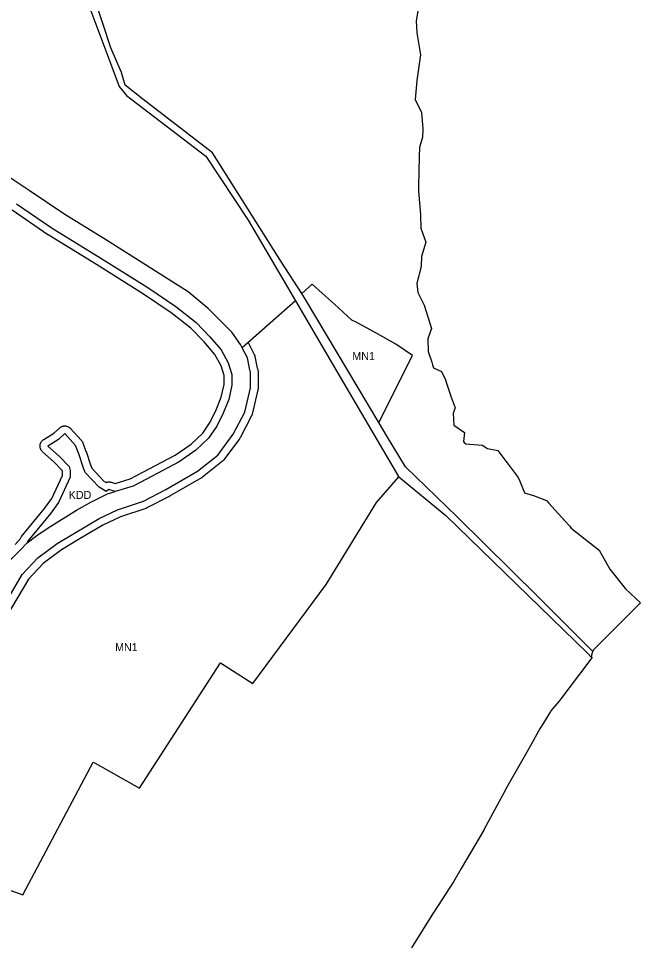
# Model space of a CAD drawing. Extents: x 7435758 to 7439981, y 5550649 to 5554049.
# Drawn here: x 7439577 to 7439981, y 5552845 to 5553445 of the extents above; entities that cross this region are included whole.
import ezdxf

# ---------------------------------------------------------------- set-up
doc = ezdxf.new("R2010")
doc.units = 0
for name, color, linetype in [('linie_rozgraniczające', 7, 'Continuous'), ('linie_zabudowy_nieprzekraczalne', 7, 'Continuous'), ('oznaczenia_przeznaczen', 7, 'Continuous')]:
    doc.layers.add(name, color=color, linetype=linetype)

msp = doc.modelspace()

# ---------------------------------------------------------------- linework, layer by layer
at = {"layer": 'linie_rozgraniczające'}
for p, q in [((7439600.88, 5553512.3), (7439637.66, 5553413.68)), ((7439636.99, 5553425.88), (7439626.65, 5553457.88)), ((7439837.74, 5553455.94), (7439835.78, 5553444.79)), ((7439835.78, 5553444.79), (7439835.56, 5553443.54)), ((7439835.56, 5553443.54), (7439836.05, 5553435.64)), ((7439836.05, 5553435.64), (7439838.25, 5553421.48)), ((7439644.02, 5553409.86), (7439636.99, 5553425.88)), ((7439838.25, 5553421.48), (7439836.79, 5553410.83)), ((7439637.66, 5553413.68), (7439642.44, 5553400.76)), ((7439836.79, 5553410.83), (7439835.95, 5553404.71)), ((7439646.47, 5553401.81), (7439644.02, 5553409.86)), ((7439835.95, 5553404.71), (7439834.94, 5553392.49)), ((7439642.44, 5553400.76), (7439647.28, 5553394.93)), ((7439657.82, 5553392.7), (7439646.47, 5553401.81)), ((7439647.28, 5553394.93), (7439698.84, 5553355.57)), ((7439703.19, 5553357.69), (7439657.82, 5553392.7)), ((7439834.94, 5553392.49), (7439839.02, 5553383.87)), ((7439839.02, 5553383.87), (7439839.82, 5553373.41)), ((7439839.82, 5553373.41), (7439839.62, 5553367.85)), ((7439839.62, 5553367.85), (7439837.58, 5553361.13)), ((7439748.06, 5553286.69), (7439703.19, 5553357.69)), ((7439837.58, 5553361.13), (7439837.46, 5553355.42)), ((7439698.84, 5553355.57), (7439726.22, 5553313.97)), ((7439837.46, 5553355.42), (7439837.26, 5553345.78)), ((7439584.03, 5553333.24), (7439566.36, 5553345.02)), ((7439837.26, 5553345.78), (7439837.06, 5553335.9)), ((7439607.06, 5553317.76), (7439584.03, 5553333.24)), ((7439837.06, 5553335.9), (7439837, 5553332.75)), ((7439837, 5553332.75), (7439838.27, 5553317.73)), ((7439575.65, 5553324.69), (7439598.96, 5553308.71)), ((7439634.18, 5553301.02), (7439607.06, 5553317.76)), ((7439838.27, 5553317.73), (7439838.33, 5553317.13)), ((7439838.33, 5553317.13), (7439838.65, 5553308.8)), ((7439598.96, 5553308.71), (7439630.48, 5553289.41)), ((7439726.22, 5553313.97), (7439757.05, 5553261.56)), ((7439838.65, 5553308.8), (7439841.86, 5553299.67)), ((7439687.37, 5553267.5), (7439634.18, 5553301.02)), ((7439841.2, 5553297.6), (7439838.89, 5553290.32)), ((7439841.86, 5553299.67), (7439841.2, 5553297.6)), ((7439630.48, 5553289.41), (7439661.08, 5553270.21)), ((7439761.15, 5553266.28), (7439748.06, 5553286.69)), ((7439838.89, 5553290.32), (7439838.76, 5553284.12)), ((7439838.76, 5553284.12), (7439836.94, 5553276.97)), ((7439836.58, 5553275.58), (7439835.91, 5553272.94)), ((7439835.91, 5553272.94), (7439836.66, 5553266.92)), ((7439836.94, 5553276.97), (7439836.58, 5553275.58)), ((7439661.08, 5553270.21), (7439679.29, 5553257.92)), ((7439700.31, 5553256.56), (7439687.37, 5553267.5)), ((7439767.84, 5553272.4), (7439761.15, 5553266.28)), ((7439774.65, 5553266.36), (7439767.84, 5553272.4)), ((7439836.66, 5553266.92), (7439836.85, 5553266.54)), ((7439757.05, 5553261.56), (7439722.38, 5553231.16)), ((7439757.05, 5553261.56), (7439786.17, 5553212.04)), ((7439763.57, 5553262.51), (7439761.15, 5553266.28)), ((7439811.19, 5553182.58), (7439763.57, 5553262.51)), ((7439782.48, 5553259.39), (7439774.65, 5553266.36)), ((7439836.85, 5553266.54), (7439840.75, 5553258.73)), ((7439679.29, 5553257.92), (7439692.48, 5553247.52)), ((7439715.78, 5553241.3), (7439700.31, 5553256.56)), ((7439793.78, 5553249.03), (7439782.48, 5553259.39)), ((7439840.75, 5553258.73), (7439840.76, 5553258.7)), ((7439840.76, 5553258.7), (7439845.51, 5553243.61)), ((7439796.53, 5553247.7), (7439793.78, 5553249.03)), ((7439692.48, 5553247.52), (7439701.45, 5553238.25)), ((7439810.35, 5553240.21), (7439796.53, 5553247.7)), ((7439845.51, 5553243.61), (7439843.47, 5553238.15)), ((7439701.45, 5553238.25), (7439708.83, 5553229.69)), ((7439721.32, 5553233.19), (7439715.78, 5553241.3)), ((7439822.25, 5553233.53), (7439810.35, 5553240.21)), ((7439843.47, 5553238.15), (7439843.02, 5553236.95)), ((7439843.02, 5553236.95), (7439843.39, 5553228.59)), ((7439722.38, 5553231.16), (7439721.32, 5553233.19)), ((7439725.84, 5553224.52), (7439722.38, 5553231.16)), ((7439833.15, 5553226.11), (7439822.25, 5553233.53)), ((7439708.83, 5553229.69), (7439713.34, 5553221.28)), ((7439811.19, 5553182.58), (7439833.15, 5553226.11)), ((7439843.39, 5553228.59), (7439845.62, 5553221.73)), ((7439713.34, 5553221.28), (7439715.72, 5553213.82)), ((7439727.46, 5553216.51), (7439725.84, 5553224.52)), ((7439845.62, 5553221.73), (7439846.16, 5553220.07)), ((7439846.16, 5553220.07), (7439846.79, 5553218.12)), ((7439715.72, 5553213.82), (7439715.75, 5553206.79)), ((7439727.74, 5553215.81), (7439727.46, 5553216.51)), ((7439727.8, 5553205.01), (7439727.74, 5553215.81)), ((7439846.79, 5553218.12), (7439851.88, 5553215.65)), ((7439851.88, 5553215.65), (7439854.6, 5553210.39)), ((7439715.75, 5553206.79), (7439713.65, 5553197.46)), ((7439786.17, 5553212.04), (7439824.05, 5553147.49)), ((7439854.6, 5553210.39), (7439855.76, 5553206.77)), ((7439855.76, 5553206.77), (7439858.21, 5553199.09)), ((7439724.05, 5553189.22), (7439727.8, 5553205.01)), ((7439713.65, 5553197.46), (7439710.1, 5553188.72)), ((7439858.21, 5553199.09), (7439860.93, 5553192.09)), ((7439716.67, 5553174.92), (7439724.05, 5553189.22)), ((7439860.93, 5553192.09), (7439859.66, 5553188.64)), ((7439710.1, 5553188.72), (7439706.02, 5553180.22)), ((7439859.66, 5553188.64), (7439860.08, 5553180.94)), ((7439706.02, 5553180.22), (7439700.6, 5553172.44)), ((7439816.24, 5553174.11), (7439811.19, 5553182.58)), ((7439860.08, 5553180.94), (7439866.96, 5553176.05)), ((7439603.12, 5553171.56), (7439596.04, 5553167.28)), ((7439607.13, 5553175.34), (7439603.12, 5553171.56)), ((7439614.15, 5553167.65), (7439607.13, 5553175.34)), ((7439700.6, 5553172.44), (7439692.33, 5553164.56)), ((7439706.52, 5553161.34), (7439716.67, 5553174.92)), ((7439828.58, 5553153.88), (7439816.24, 5553174.11)), ((7439866.96, 5553176.05), (7439866.17, 5553170.16)), ((7439596.04, 5553167.28), (7439603.38, 5553160.69)), ((7439616.19, 5553162.12), (7439614.15, 5553167.65)), ((7439866.17, 5553170.16), (7439866.69, 5553169.69)), ((7439866.69, 5553169.69), (7439867.83, 5553168.68)), ((7439867.83, 5553168.68), (7439878.42, 5553167.89)), ((7439878.42, 5553167.89), (7439881.85, 5553165.76)), ((7439881.85, 5553165.76), (7439888.61, 5553164.3)), ((7439603.38, 5553160.69), (7439610, 5553153.89)), ((7439619.07, 5553153.53), (7439616.19, 5553162.12)), ((7439692.33, 5553164.56), (7439681.43, 5553157.08)), ((7439693.5, 5553150.93), (7439706.52, 5553161.34)), ((7439888.61, 5553164.3), (7439893.75, 5553157.52)), ((7439610, 5553153.89), (7439610.64, 5553151.38)), ((7439620.3, 5553150.14), (7439619.07, 5553153.53)), ((7439681.43, 5553157.08), (7439660.27, 5553145.8)), ((7439862.15, 5553121.22), (7439828.58, 5553153.88)), ((7439893.75, 5553157.52), (7439894.7, 5553156.27)), ((7439894.7, 5553156.27), (7439901.85, 5553146.85)), ((7439610.64, 5553147.03), (7439603.15, 5553130.59)), ((7439610.64, 5553151.38), (7439610.64, 5553147.03)), ((7439629.39, 5553140.54), (7439620.3, 5553150.14)), ((7439672.71, 5553138.98), (7439693.5, 5553150.93)), ((7439809.8, 5553130.68), (7439824.25, 5553147.33)), ((7439824.05, 5553147.49), (7439824.25, 5553147.33)), ((7439824.25, 5553147.33), (7439854.85, 5553122.16)), ((7439901.85, 5553146.85), (7439902.79, 5553144.53)), ((7439651.6, 5553141.28), (7439639.85, 5553137.7)), ((7439660.27, 5553145.8), (7439651.6, 5553141.28)), ((7439902.79, 5553144.53), (7439905.89, 5553136.94)), ((7439624.15, 5553130.79), (7439634.87, 5553136.18)), ((7439634.03, 5553137.83), (7439629.39, 5553140.54)), ((7439635.8, 5553138.99), (7439634.03, 5553137.83)), ((7439634.87, 5553136.18), (7439639.85, 5553137.7)), ((7439639.85, 5553137.7), (7439635.8, 5553138.99)), ((7439658.2, 5553131.53), (7439672.71, 5553138.98)), ((7439905.89, 5553136.94), (7439911.7, 5553135.12)), ((7439911.7, 5553135.12), (7439920.18, 5553131.88)), ((7439603.15, 5553130.59), (7439597.99, 5553123.68)), ((7439614.72, 5553125.72), (7439624.15, 5553130.79)), ((7439641.41, 5553125.91), (7439658.2, 5553131.53)), ((7439776.92, 5553077.3), (7439809.8, 5553130.68)), ((7439920.18, 5553131.88), (7439921.71, 5553130.12)), ((7439921.71, 5553130.12), (7439932.11, 5553118.71)), ((7439597.99, 5553123.68), (7439582.97, 5553105.31)), ((7439596.31, 5553114.17), (7439614.72, 5553125.72)), ((7439629.57, 5553120.21), (7439641.41, 5553125.91)), ((7439613.49, 5553110.78), (7439629.57, 5553120.21)), ((7439854.85, 5553122.16), (7439946.7, 5553033.04)), ((7439914.94, 5553069.14), (7439862.15, 5553121.22)), ((7439932.11, 5553118.71), (7439935.33, 5553115.16)), ((7439588.96, 5553109.18), (7439596.31, 5553114.17)), ((7439935.33, 5553115.16), (7439936.35, 5553114.04)), ((7439936.35, 5553114.04), (7439954.4, 5553099.6)), ((7439582.76, 5553104.51), (7439588.96, 5553109.18)), ((7439582.97, 5553105.31), (7439582.76, 5553104.51)), ((7439602.24, 5553104.01), (7439613.49, 5553110.78)), ((7439578.39, 5553099.9), (7439572.13, 5553093.65)), ((7439582.38, 5553104.23), (7439578.39, 5553099.9)), ((7439582.76, 5553104.51), (7439582.38, 5553104.23)), ((7439589.72, 5553094.72), (7439602.24, 5553104.01)), ((7439954.4, 5553099.6), (7439961.29, 5553087.41)), ((7439579.46, 5553083.88), (7439589.72, 5553094.72)), ((7439961.29, 5553087.41), (7439971.62, 5553074.6)), ((7439564.69, 5553059), (7439579.46, 5553083.88)), ((7439729.26, 5553013.06), (7439776.92, 5553077.3)), ((7439950.32, 5553033.89), (7439914.94, 5553069.14)), ((7439971.62, 5553074.6), (7439981.35, 5553065.42)), ((7439980.28, 5553064.31), (7439978.3, 5553062.33)), ((7439981.35, 5553065.42), (7439980.28, 5553064.31)), ((7439978.3, 5553062.33), (7439950.55, 5553034.58)), ((7439946.7, 5553033.04), (7439949.59, 5553029.62)), ((7439949.98, 5553032.93), (7439949.15, 5553030.6)), ((7439950.32, 5553033.89), (7439949.98, 5553032.93)), ((7439950.55, 5553034.58), (7439950.32, 5553033.89)), ((7439948.97, 5553028.81), (7439928.16, 5553001.38)), ((7439949.59, 5553029.62), (7439948.97, 5553028.81)), ((7439949.15, 5553030.6), (7439949.76, 5553029.84)), ((7439949.76, 5553029.84), (7439949.59, 5553029.62)), ((7439655.72, 5552945.12), (7439708.35, 5553026.55)), ((7439708.35, 5553026.55), (7439729.26, 5553013.06)), ((7439928.16, 5553001.38), (7439923.07, 5552995.32)), ((7439922.79, 5552994.9), (7439918, 5552987.06)), ((7439923.07, 5552995.32), (7439922.79, 5552994.9)), ((7439918, 5552987.06), (7439916.17, 5552984.07)), ((7439916.17, 5552984.07), (7439909.36, 5552971.96)), ((7439907.4, 5552968.48), (7439893.64, 5552944.14)), ((7439909.36, 5552971.96), (7439907.4, 5552968.48)), ((7439579.94, 5552875.84), (7439625.65, 5552961.95)), ((7439625.65, 5552961.95), (7439626.78, 5552961.32)), ((7439626.78, 5552961.32), (7439655.72, 5552945.12)), ((7439893.51, 5552943.89), (7439879.47, 5552917.91)), ((7439893.64, 5552944.14), (7439893.51, 5552943.89)), ((7439458.23, 5552917.63), (7439579.94, 5552875.84)), ((7439879.41, 5552917.8), (7439864.72, 5552892.88)), ((7439879.47, 5552917.91), (7439879.41, 5552917.8)), ((7439864.7, 5552892.85), (7439859.69, 5552884.24)), ((7439864.72, 5552892.88), (7439864.7, 5552892.85)), ((7439859.69, 5552884.24), (7439847.01, 5552864.42)), ((7439846.87, 5552864.2), (7439832.42, 5552841.4)), ((7439847.01, 5552864.42), (7439846.87, 5552864.2))]:
    msp.add_line(p, q, dxfattribs=at)
at = {"layer": 'linie_zabudowy_nieprzekraczalne'}
for points in [[(7439574.79, 5553103.36), (7439578.36, 5553107.23), (7439578.4, 5553107.33), (7439578.54, 5553107.63), (7439578.7, 5553107.91), (7439578.88, 5553108.18), (7439579.08, 5553108.45), (7439579.1, 5553108.47), (7439594.05, 5553126.76), (7439598.82, 5553133.15), (7439605.64, 5553148.12), (7439605.64, 5553150.75), (7439605.49, 5553151.36), (7439599.91, 5553157.08), (7439592.7, 5553163.56), (7439592.65, 5553163.61), (7439592.42, 5553163.84), (7439592.2, 5553164.08), (7439592, 5553164.34), (7439591.82, 5553164.61), (7439591.65, 5553164.89), (7439591.5, 5553165.18), (7439591.38, 5553165.48), (7439591.27, 5553165.79), (7439591.18, 5553166.11), (7439591.11, 5553166.43), (7439591.07, 5553166.75), (7439591.04, 5553167.08), (7439591.04, 5553167.41), (7439591.06, 5553167.73), (7439591.1, 5553168.06), (7439591.16, 5553168.38), (7439591.24, 5553168.7), (7439591.35, 5553169.01), (7439591.47, 5553169.31), (7439591.61, 5553169.6), (7439591.77, 5553169.89), (7439591.95, 5553170.16), (7439592.15, 5553170.42), (7439592.36, 5553170.67), (7439592.59, 5553170.9), (7439592.84, 5553171.12), (7439593.1, 5553171.32), (7439593.37, 5553171.51), (7439593.46, 5553171.56), (7439600.08, 5553175.56), (7439603.7, 5553178.98), (7439603.93, 5553179.18), (7439604.19, 5553179.39), (7439604.46, 5553179.57), (7439604.74, 5553179.74), (7439605.03, 5553179.88), (7439605.33, 5553180.01), (7439605.64, 5553180.12), (7439605.96, 5553180.2), (7439606.28, 5553180.27), (7439606.6, 5553180.32), (7439606.93, 5553180.34), (7439607.26, 5553180.34), (7439607.58, 5553180.32), (7439607.91, 5553180.28), (7439608.23, 5553180.22), (7439608.55, 5553180.14), (7439608.86, 5553180.04), (7439609.16, 5553179.91), (7439609.45, 5553179.77), (7439609.74, 5553179.61), (7439610.01, 5553179.43), (7439610.27, 5553179.23), (7439610.52, 5553179.02), (7439610.75, 5553178.79), (7439610.83, 5553178.72), (7439617.84, 5553171.02), (7439617.99, 5553170.86), (7439618.19, 5553170.6), (7439618.38, 5553170.33), (7439618.54, 5553170.05), (7439618.69, 5553169.75), (7439618.82, 5553169.45), (7439618.84, 5553169.38), (7439620.88, 5553163.84), (7439620.93, 5553163.71), (7439623.8, 5553155.18), (7439624.65, 5553152.82), (7439632.53, 5553144.5), (7439633.98, 5553143.65), (7439634, 5553143.65), (7439634.31, 5553143.76), (7439634.62, 5553143.85), (7439634.94, 5553143.91), (7439635.27, 5553143.96), (7439635.59, 5553143.98), (7439635.92, 5553143.99), (7439636.25, 5553143.97), (7439636.57, 5553143.93), (7439636.89, 5553143.87), (7439637.21, 5553143.78), (7439637.22, 5553143.78), (7439637.31, 5553143.75), (7439639.88, 5553142.93), (7439649.69, 5553145.93), (7439657.94, 5553150.23), (7439678.83, 5553161.36), (7439689.17, 5553168.45), (7439696.79, 5553175.71), (7439701.68, 5553182.74), (7439705.53, 5553190.74), (7439708.86, 5553198.96), (7439710.75, 5553207.33), (7439710.73, 5553213.03), (7439708.71, 5553219.32), (7439704.68, 5553226.84), (7439697.76, 5553234.87), (7439689.12, 5553243.8), (7439676.34, 5553253.88), (7439658.35, 5553266.02), (7439627.84, 5553285.17), (7439596.35, 5553304.45), (7439596.13, 5553304.59), (7439572.86, 5553320.55)], [(7439726.25, 5553234.55), (7439730.27, 5553226.83), (7439730.37, 5553226.62), (7439730.5, 5553226.32), (7439730.61, 5553226.01), (7439730.7, 5553225.69), (7439730.74, 5553225.51), (7439732.28, 5553217.93), (7439732.39, 5553217.64), (7439732.41, 5553217.61), (7439732.51, 5553217.3), (7439732.6, 5553216.98), (7439732.67, 5553216.66), (7439732.71, 5553216.34), (7439732.74, 5553216.01), (7439732.74, 5553215.84), (7439732.8, 5553205.04), (7439732.79, 5553204.89), (7439732.78, 5553204.56), (7439732.74, 5553204.23), (7439732.67, 5553203.91), (7439732.66, 5553203.85), (7439728.91, 5553188.06), (7439728.84, 5553187.8), (7439728.74, 5553187.49), (7439728.62, 5553187.19), (7439728.49, 5553186.92), (7439721.11, 5553172.63), (7439721.1, 5553172.6), (7439720.94, 5553172.32), (7439720.76, 5553172.04), (7439720.67, 5553171.93), (7439710.52, 5553158.35), (7439710.41, 5553158.2), (7439710.19, 5553157.95), (7439709.96, 5553157.72), (7439709.72, 5553157.5), (7439709.64, 5553157.43), (7439696.62, 5553147.03), (7439696.44, 5553146.89), (7439696.17, 5553146.71), (7439695.99, 5553146.6), (7439675.21, 5553134.64), (7439675.11, 5553134.59), (7439675, 5553134.53), (7439660.48, 5553127.08), (7439660.3, 5553126.99), (7439660, 5553126.86), (7439659.79, 5553126.79), (7439643.3, 5553121.27), (7439631.92, 5553115.8), (7439616.04, 5553106.48), (7439605.02, 5553099.85), (7439593.05, 5553090.97), (7439583.47, 5553080.85), (7439568.99, 5553056.44)]]:
    msp.add_lwpolyline(points, dxfattribs=at)

# ---------------------------------------------------------------- texts
at = {"layer": 'oznaczenia_przeznaczen'}
for s, p in [('MN1', (7439794.02, 5553223.15)), ('KDD', (7439609.7, 5553132.92)), ('MN1', (7439639.82, 5553034.04))]:
    msp.add_text(s, height=5.2, dxfattribs=at).set_placement(p)

doc.saveas('drawing.dxf')
